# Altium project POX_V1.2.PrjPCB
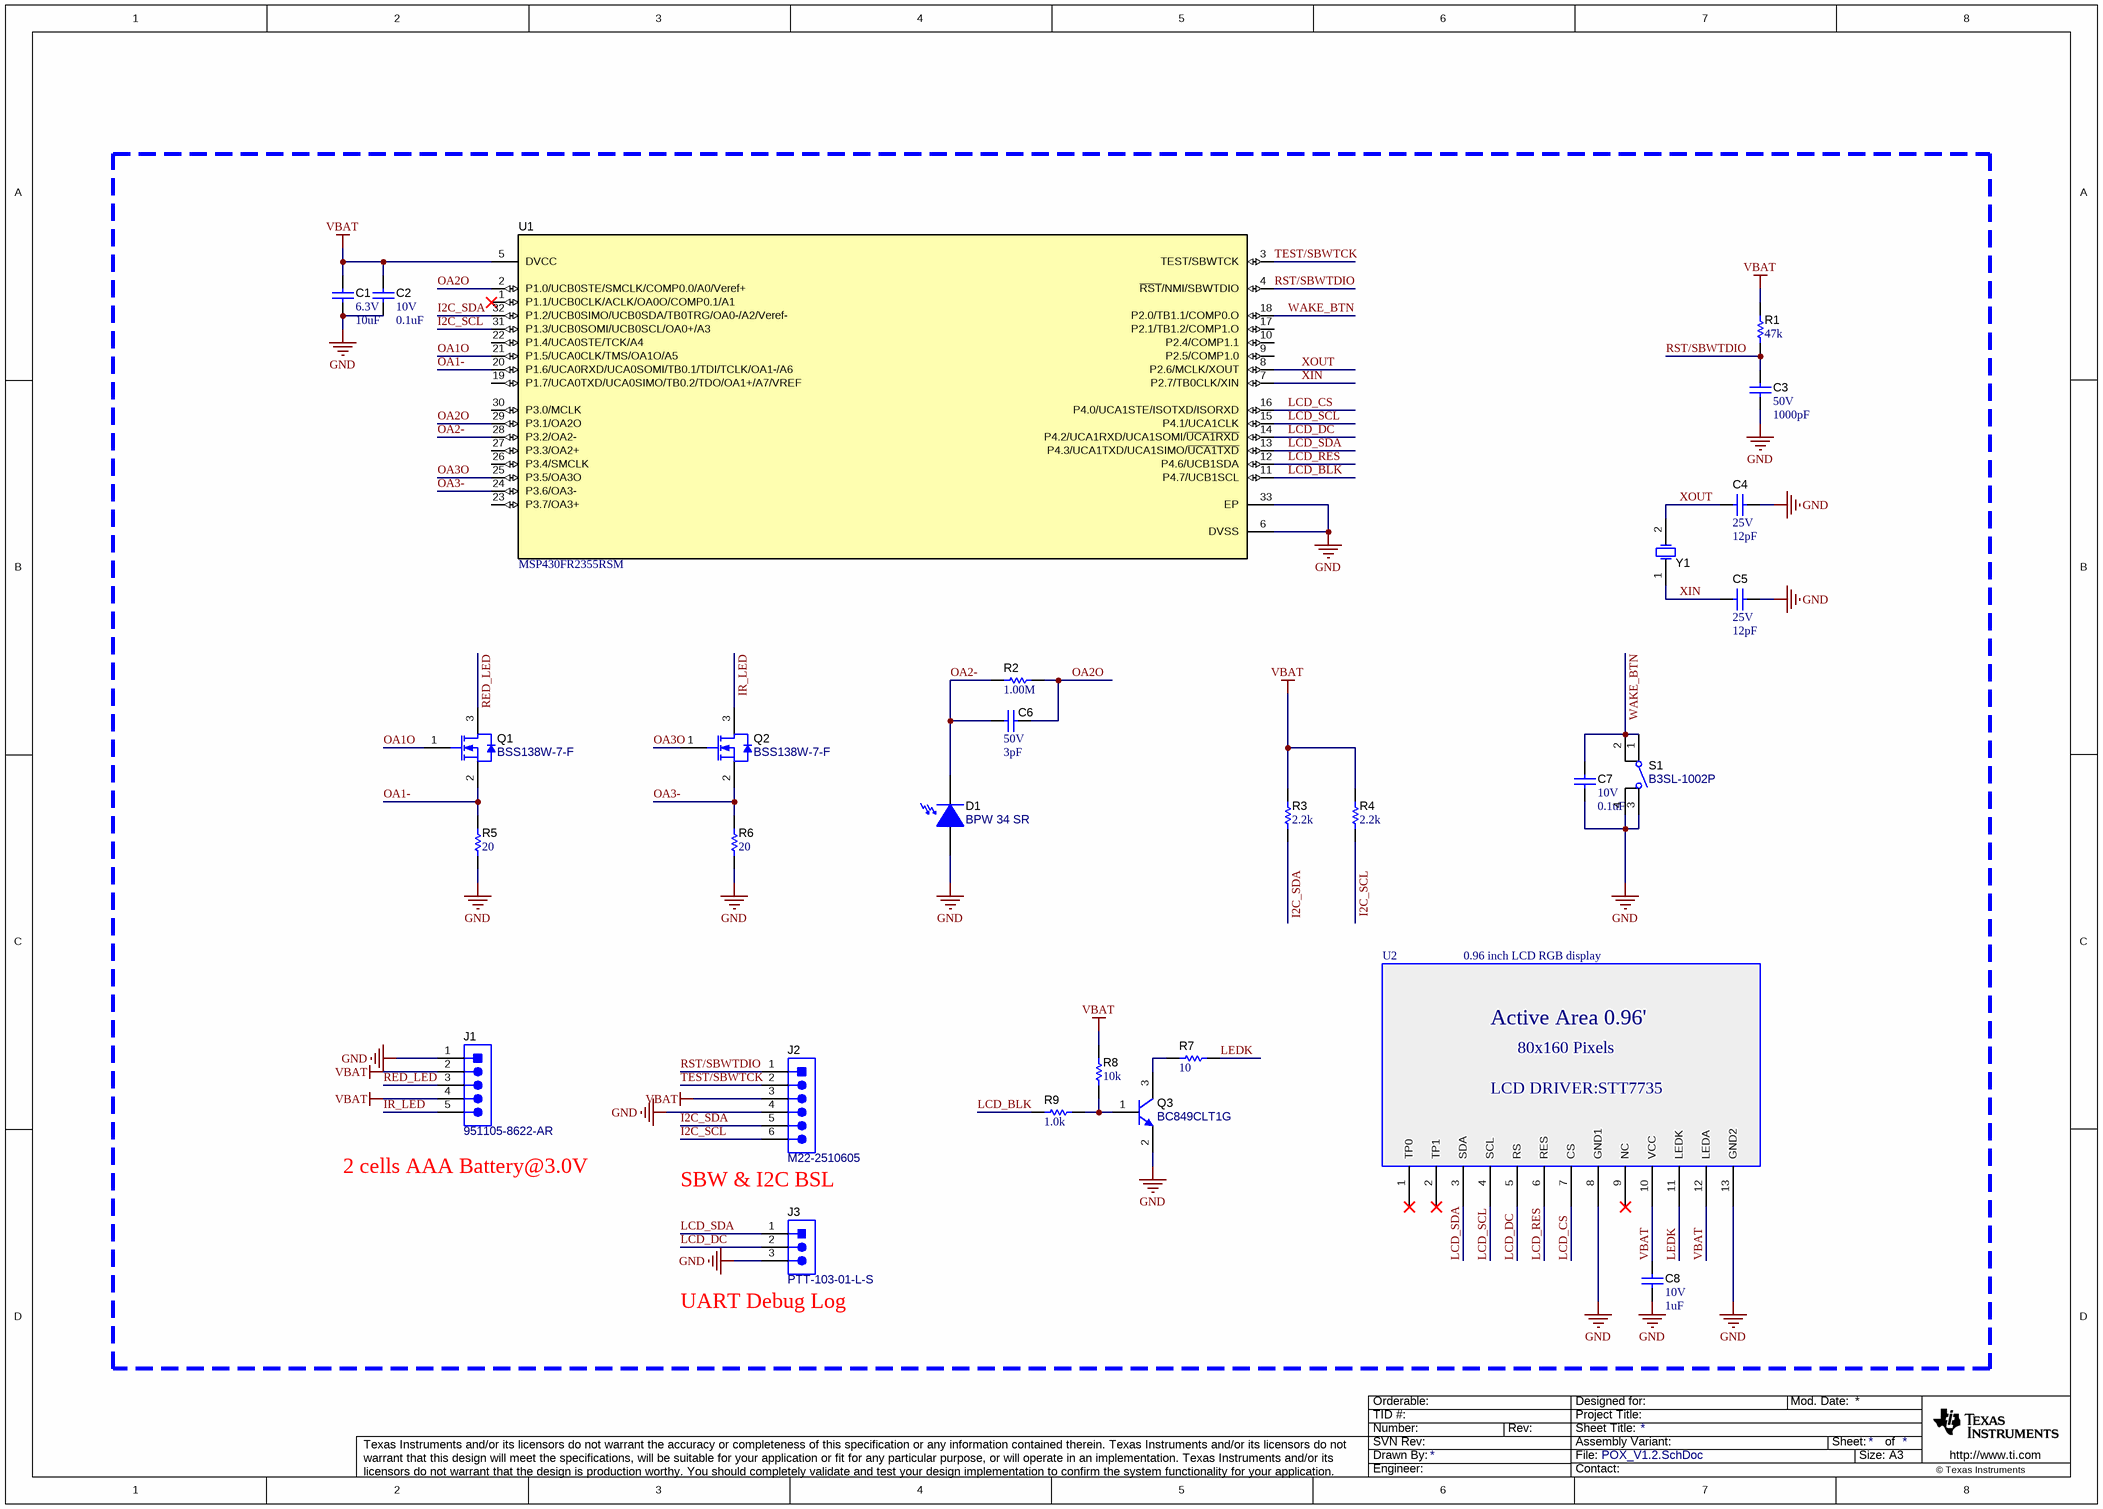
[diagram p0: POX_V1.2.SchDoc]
1 sheet, 28 parts. Net scope: global (net labels, ports and power ports of the same name join across sheets).
Board file: POX_V1.2.PcbDoc

## Sheet POX_V1.2.SchDoc
size A3; PageSetup: Record=PageOptions¦CenterHorizontal=True¦CenterVertical=True¦PrintScale=0.69¦XCorrection=1.00¦YCorrection=1.00¦PrintKind=0¦BorderSize=5000000¦LeftOffset=0¦BottomOffset=0¦Orientation=2¦PaperLength=1000¦PaperWidth=1000¦Scale=100¦PaperSource=15¦PrintQuality=600¦MediaType=1¦DitherType=10¦PaperKind=Letter¦PrintScaleMode=1

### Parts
C1  VDC_V: 6.3V  ValueDisplayed: 10uF  [0603L]  (hidden comment: GRM188R60J106ME84)
C2  VDC_V: 10V  ValueDisplayed: 0.1uF  [0402L]  (hidden comment: GRM155R61A104KA01D)
C3  VDC_V: 50V  ValueDisplayed: 1000pF  [0402L]  (hidden comment: C1005NP01H102J050BA)
C4  VDC_V: 25V  ValueDisplayed: 12pF  [0402L]  (hidden comment: GRM1555C1E120JA01D)
C5  VDC_V: 25V  ValueDisplayed: 12pF  [0402L]  (hidden comment: GRM1555C1E120JA01D)
C6  VDC_V: 50V  ValueDisplayed: 3pF  [0402L]  (hidden comment: GRM1555C1H1R0CA01D)
C7  VDC_V: 10V  ValueDisplayed: 0.1uF  [0402L]  (hidden comment: GRM155R61A104KA01D)
C8  VDC_V: 10V  ValueDisplayed: 1uF  [0402L]  (hidden comment: GRM155R61A105KE15D)
D1  BPW 34 SR  [BPW34SR]
J1  951105-8622-AR  [3M_951105-8622-AR]
J2  M22-2510605  [Harwin_M22-25106]
J3  PTT-103-01-L-S  [Samtec_PTT-103-01-x-S]
Q1  BSS138W-7-F  [SOT-323]
Q2  BSS138W-7-F  [SOT-323]
Q3  BC849CLT1G  [SOT-23]
R1  ValueDisplayed: 47k  [0402L]  (hidden comment: CRCW040247K0JNED)
R2  ValueDisplayed: 1.00M  [0402]  (hidden comment: CRCW04021M00FKED)
R3  ValueDisplayed: 2.2k  [0402L]  (hidden comment: CRCW04022K20JNED)
R4  ValueDisplayed: 2.2k  [0402L]  (hidden comment: CRCW04022K20JNED)
R5  ValueDisplayed: 20  [0402L]  (hidden comment: 504L50R0FTNCFT)
R6  ValueDisplayed: 20  [0402L]  (hidden comment: 504L50R0FTNCFT)
R7  ValueDisplayed: 10  [0402L]  (hidden comment: CRCW040210R0JNED)
R8  ValueDisplayed: 10k  [0402L]  (hidden comment: CRCW040210K0JNED)
R9  ValueDisplayed: 1.0k  [0402L]  (hidden comment: CRCW04021K00JNED)
S1  B3SL-1002P  [SW_B3SL-1002P]
U1  MSP430FR2355RSM  [RSM0032B]
U2  0.96 inch LCD RGB display  [GMT096-01]
Y1  ECS-.327-12.5-34B-TR  [ECS_ECX_31B]  (value not drawn)

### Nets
GND: C1.2 C2.1 C3.2 C4.2 C5.2 C7.2 C8.1 D1.1(A) J1.1 J2.4 J3.3 Q3.2(E) R5.1 R6.1 S1.3 S1.4 U1.6(DVSS) U1.33(EP) U2.8(GND1) U2.13(GND2)
VBAT: C1.1 C2.2 C8.2 J1.2 J1.4 J2.3 R1.2 R3.2 R4.2 R8.2 U1.5(DVCC) U2.10(VCC) U2.12(LEDA)
I2C_SCL: J2.6 R4.1 U1.31(P1.3/UCB0SOMI/UCB0SCL/OA0+/A3)
I2C_SDA: J2.5 R3.1 U1.32(P1.2/UCB0SIMO/UCB0SDA/TB0TRG/OA0-/A2/Veref-)
IR_LED: J1.5 Q2.3(D)
LCD_BLK: R9.1 U1.11(P4.7/UCB1SCL)
LCD_CS: U1.16(P4.0/UCA1STE/ISOTXD/ISORXD) U2.7(CS)
LCD_DC: J3.2 U1.14(P4.2/UCA1RXD/UCA1SOMI/~{UCA1RXD}) U2.5(RS)
LCD_RES: U1.12(P4.6/UCB1SDA) U2.6(RES)
LCD_SCL: U1.15(P4.1/UCA1CLK) U2.4(SCL)
LCD_SDA: J3.1 U1.13(P4.3/UCA1TXD/UCA1SIMO/~{UCA1TXD}) U2.3(SDA)
LEDK: R7.2 U2.11(LEDK)
OA1-: Q1.2(S) R5.2 U1.20(P1.6/UCA0RXD/UCA0SOMI/TB0.1/TDI/TCLK/OA1-/A6)
OA1O: Q1.1(G) U1.21(P1.5/UCA0CLK/TMS/OA1O/A5)
OA2-: C6.2 D1.2(C) R2.1 U1.28(P3.2/OA2-)
OA2O: C6.1 R2.2 U1.2(P1.0/UCB0STE/SMCLK/COMP0.0/A0/Veref+) U1.29(P3.1/OA2O)
OA3-: Q2.2(S) R6.2 U1.24(P3.6/OA3-)
OA3O: Q2.1(G) U1.25(P3.5/OA3O)
RED_LED: J1.3 Q1.3(D)
RST/SBWTDIO: C3.1 J2.1 R1.1 U1.4(~{RST}/NMI/SBWTDIO)
TEST/SBWTCK: J2.2 U1.3(TEST/SBWTCK)
WAKE_BTN: C7.1 S1.1 S1.2 U1.18(P2.0/TB1.1/COMP0.O)
XIN: C5.1 U1.7(P2.7/TB0CLK/XIN) Y1.1(OSC1)
XOUT: C4.1 U1.8(P2.6/MCLK/XOUT) Y1.2(OSC2)
NetQ3_1: Q3.1(B) R8.1 R9.2
NetQ3_3: Q3.3(C) R7.1

Not connected (* = marked no-connect by the designer): U1 1(P1.1/UCB0CLK/ACLK/OA0O/COMP0.1/A1)* 9(P2.5/COMP1.0) 10(P2.4/COMP1.1) 17(P2.1/TB1.2/COMP1.O) 19(P1.7/UCA0TXD/UCA0SIMO/TB0.2/TDO/OA1+/A7/VREF) 22(P1.4/UCA0STE/TCK/A4) 23(P3.7/OA3+) 26(P3.4/SMCLK) 27(P3.3/OA2+) 30(P3.0/MCLK); U2 1(TP0)* 2(TP1)* 9(NC)*

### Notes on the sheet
- (near J1) 2 cells AAA Battery@3.0V
- SBW & I2C BSL
- (near J3) UART Debug Log

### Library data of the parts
C1 = CMP-0007304-5: CAP, CERM, 10 uF, 6.3 V, +/- 20%, X5R, 0603; Manufacturer: MuRata; TaMin_C: -55°C; Polarized: N; SizeAreaWB_mm2: 4.68; Value1: Unknown; U/M: EA; Value: 10uF; TaMax_C: 85°C; SizeZ_mm: 1; SizeX_mm: 1.6; SizeY_mm: 0.8; Cap_Case: 0603; SizeArea_mm2: 1.28; Cap_F: 10µF; AEC Category: Q200
C2 C7 = CMP-0006562-2: CAP, CERM, 0.1 uF, 10 V, +/- 10%, X5R, 0402; Manufacturer: MuRata; TaMin_C: -55°C; Polarized: N; SizeAreaWB_mm2: 3; Value1: Unknown; U/M: EA; Value: 0.1uF; TaMax_C: 85°C; SizeZ_mm: 0.6; SizeX_mm: 1; SizeY_mm: 0.5; Cap_Case: 0402; Cap_F: 100nF; AEC Category: Q200
C3 = CMP-0006254-2: CAP, CERM, 1000 pF, 50 V, +/- 5%, C0G/NP0, 0402; Manufacturer: TDK; TaMin_C: -55°C; Polarized: N; SizeAreaWB_mm2: 3; Value1: Unknown; U/M: EA; Value: 1000pF; TaMax_C: 150°C; SizeZ_mm: 0.6; SizeX_mm: 1; SizeY_mm: 0.5; Cap_Case: 0402; Cap_F: 1nF; AEC Category: Q200
C4 C5 = CMP-0006375-2: CAP, CERM, 12 pF, 25 V, +/- 5%, C0G/NP0, 0402; Manufacturer: MuRata; TaMin_C: -55°C; Polarized: N; SizeAreaWB_mm2: 3; Value1: Unknown; U/M: EA; Value: 12pF; TaMax_C: 125°C; SizeZ_mm: 0.6; SizeX_mm: 1; SizeY_mm: 0.5; Cap_Case: 0402; AEC Category: Q200
C6 = CMP-0006427-2: CAP, CERM, 1 pF, 50 V, +/- 5%, C0G/NP0, 0402; Manufacturer: MuRata; TaMin_C: -55°C; Polarized: N; SizeAreaWB_mm2: 3; Value1: Unknown; U/M: EA; Value: 1pF; TaMax_C: 125°C; SizeZ_mm: 0.6; SizeX_mm: 1; SizeY_mm: 0.5; Cap_Case: 0402; AEC Category: Q200
C8 = CMP-0006563-2: CAP, CERM, 1 uF, 10 V, +/- 10%, X5R, 0402; Manufacturer: MuRata; TaMin_C: -55°C; Polarized: N; SizeAreaWB_mm2: 3; Value1: Unknown; U/M: EA; Value: 1uF; TaMax_C: 85°C; SizeZ_mm: 0.6; SizeX_mm: 1; SizeY_mm: 0.5; Cap_Case: 0402; Cap_F: 1µF; AEC Category: Q200
D1 = CMP-0005335-2: PIN Photodiode, SMD; Manufacturer: OSRAM
J1 = CMP-0075215-1: Header, 2mm, 5x1, Gold, Black, TH; Manufacturer: 3M; CNHeader: True; Current_A: 1A; Gender: Male; Voltage_V: 1kV; Row_Count: 1; Pitch_mm: 2; CT: False; Cert_UL: Y
J2 = CMP-0075299-1: Header, 2mm, 6x1, Gold, TH; Manufacturer: Harwin; CNHeader: True; Current_A: 1A; Shrouded: N; Gender: Male; Voltage_V: 500V; Row_Count: 1; Pitch_mm: 2; CT: False
J3 = CMP-0055571-1: Header, 2mm, 3x1, Gold, TH; Manufacturer: Samtec; CNHeader: TRUE; Current_A: 2.9A; Shrouded: N; Gender: Male; Pitch_mm: 2; CT: FALSE; Cert_UL: Y
Q1 Q2 = CMP-0000757-1: MOSFET, N-CH, 50 V, 0.2 A, SOT-323; Alternate Manufacturer: None; Manufacturer: Diodes Inc.; SizeZ_mm: 1.1; ChType: N; Value1: 3; VdsMax_V: 50V; SizeX_mm: 2.2; Vgs_V: 1.5V; Value: 50V; Rdson45_ohm: 3.5; SizeArea_mm2: 4.84; AEC Category: Q101; IdsMax_A: 200mA; SizeAreaWB_mm2: 10.24; U/M: EA
Q3 = CMP-0000378-2: Transistor, NPN, 30 V, 0.1 A, SOT-23; Manufacturer: ON Semiconductor; TaMax_C: 150°C; Value2: 800; Value1: 0.1 A; Vcesat1_V: 700mV; SizeX_mm: 2.5; SizeY_mm: 3; TaMin_C: -55°C; IcRated_A: 100mA; CompType: BJT; SizeZ_mm: 1.1; Value: 30 V; SizeArea_mm2: 7.5; NPN: 1; Vceo_V: 30V; PNP: 0; AEC Category: Q101; SizeAreaWB_mm2: 14; U/M: EA
R1 = CMP-0026935-3: RES, 47 k, 5%, 0.063 W, AEC-Q200 Grade 0, 0402; Manufacturer: Vishay-Dale; Power_W: 63mW; TempCo: 200 ppm/C; Value_Code: 47k0; Value: 47k; EIA_Code: E24; SizeX_mm: 1; SizeY_mm: 0.5; SizeZ_mm: 0.6; Value2: 0.063W; AEC Qualified: Y; VDC_V: 50V; AEC Category: Q200; AEC Grade: 0
R2 = CMP-0026100-2: RES, 1.00 M, 1%, 0.063 W, AEC-Q200 Grade 0, 0402; Manufacturer: Vishay-Dale; Power_W: 63mW; TempCo: 100 ppm/C; Value_Code: 1M00; Value: 1.00Meg; EIA_Code: E96; Res_ohm: 1M; SizeX_mm: 1; SizeY_mm: 0.5; SizeZ_mm: 0.6; Value2: 0.063W; AEC Qualified: Y; VDC_V: 50V; AEC Category: Q200; AEC Grade: 0
R3 R4 = CMP-0026890-5: RES, 2.2 k, 5%, 0.063 W, AEC-Q200 Grade 0, 0402; Manufacturer: Vishay-Dale; Power_W: 63mW; TempCo: 200 ppm/C; Value_Code: 2k20; Value: 2.2k; EIA_Code: E24; SizeX_mm: 1; SizeY_mm: 0.5; SizeZ_mm: 0.6; Value2: 0.063W; AEC Qualified: Y; VDC_V: 50V; AEC Category: Q200; AEC Grade: 0
R5 = CMP-0025948-2: RES, 20, 1%, 0.125 W, AEC-Q200 Grade 1, 0402; Manufacturer: AT Ceramics; Power_W: 125mW; TempCo: 150 ppm/C; Value_Code: 50R0; U/M: EA; Value: 50; SizeX_mm: 1; SizeY_mm: 0.5; SizeZ_mm: 0.6; Value2: 0.125W; AEC Qualified: Y; AEC Category: Q200
R6 = CMP-0025948-2: RES, 50, 1%, 0.125 W, AEC-Q200 Grade 1, 0402; Manufacturer: AT Ceramics; Power_W: 125mW; TempCo: 150 ppm/C; Value_Code: 50R0; U/M: EA; Value: 50; SizeX_mm: 1; SizeY_mm: 0.5; SizeZ_mm: 0.6; Value2: 0.125W; AEC Qualified: Y; AEC Category: Q200
R7 = CMP-0026827-3: RES, 10, 5%, 0.063 W, AEC-Q200 Grade 0, 0402; Manufacturer: Vishay-Dale; Power_W: 63mW; TempCo: 200 ppm/C; Value_Code: 10R0; Value: 10; EIA_Code: E24; SizeX_mm: 1; SizeY_mm: 0.5; SizeZ_mm: 0.6; Value2: 0.063W; AEC Qualified: Y; VDC_V: 50V; AEC Category: Q200; AEC Grade: 0
R8 = CMP-0026825-5: RES, 10 k, 5%, 0.063 W, AEC-Q200 Grade 0, 0402; Manufacturer: Vishay-Dale; Power_W: 63mW; TempCo: 200 ppm/C; Value_Code: 10k0; Value: 10k; EIA_Code: E24; SizeX_mm: 1; SizeY_mm: 0.5; SizeZ_mm: 0.6; Value2: 0.063W; AEC Qualified: Y; VDC_V: 50V; AEC Category: Q200; AEC Grade: 0
R9 = CMP-0026852-3: RES, 1.0 k, 5%, 0.063 W, AEC-Q200 Grade 0, 0402; Manufacturer: Vishay-Dale; Power_W: 63mW; TempCo: 200 ppm/C; Value_Code: 1k00; Value: 1.0k; EIA_Code: E24; Res_ohm: 1k; SizeX_mm: 1; SizeY_mm: 0.5; SizeZ_mm: 0.6; Value2: 0.063W; AEC Qualified: Y; VDC_V: 50V; AEC Category: Q200; AEC Grade: 0
S1 = CMP-0002310-1: SWITCH TACTILE SPST-NO 0.05A 12V; Manufacturer: Omron Electronic Components; CurrentRating_mA: 50A; PositionCount: 1; SizeX_mm: 6.2; SizeY_mm: 6.5; SizeZ_mm: 3.4; SizeArea_mm2: 40.3; SizeAreaWB_mm2: 69.7; SwitchFunction: Off-Mom
U1 = CMP-0860022-1: MSP430FR235x mixed-signal microcontrollers, RSM0032B (VQFN-32); Alternate Manufacturer: Texas Instruments; SizeArea_mm2: 16; AEC Qualified: N; CompType: IC; AEC Category: Q200; SizeY_mm: 4; SizeAreaWB_mm2: 25; SizeZ_mm: 1
U2 = GMT096-01
Y1 = CMP-0078856-1: Crystal, 32.768 KHz, 20 ppm, SMD; Manufacturer: ECS Inc.; SizeAreaWB_mm2: 10.5; SizeArea_mm2: 4.8; Frequency Tolerance: 20 ppm; AEC Category: Q200; TaMax_C: 85°C; SizeZ_mm: 0.9; TaMin_C: -40°C; SizeY_mm: 1.5; SizeX_mm: 3.2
